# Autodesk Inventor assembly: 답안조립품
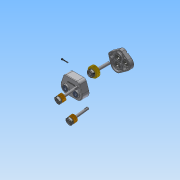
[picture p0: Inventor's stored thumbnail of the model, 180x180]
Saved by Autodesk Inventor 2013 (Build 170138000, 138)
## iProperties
Created: 2014-12
Part Number: 답안조립품
Document SubType Name: Assembly
Designer: Administrator
Author: Administrator
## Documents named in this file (14)
- C:\Users\Administrator\Desktop\441209V1016\441209V1016\답안조립품.iam
- C:\Users\Administrator\Desktop\441209V1016\441209V1016\본체.ipt
- C:\Users\Administrator\Desktop\441209V1016\441209V1016\M 5 x 35.ipt
- C:\Users\Administrator\Desktop\441209V1016\441209V1016\멈춤링.ipt
- C:\Users\Administrator\Desktop\441209V1016\441209V1016\메인기어.ipt
- C:\Users\Administrator\Desktop\441209V1016\441209V1016\메인축.ipt
- C:\Users\Administrator\Desktop\441209V1016\441209V1016\베어링- 6202.ipt
- C:\Users\Administrator\Desktop\441209V1016\441209V1016\베어링- 6203.ipt
- C:\Users\Administrator\Desktop\441209V1016\441209V1016\서브기어.ipt
- C:\Users\Administrator\Desktop\441209V1016\441209V1016\서브축.ipt
- C:\Users\Administrator\Desktop\441209V1016\441209V1016\오일시일-D-15.ipt
- C:\Users\Administrator\Desktop\441209V1016\441209V1016\오일시일-D-17.ipt
- C:\Users\Administrator\Desktop\441209V1016\441209V1016\커버.ipt
- C:\Users\Administrator\Desktop\441209V1016\441209V1016\키5x5.ipt
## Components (13 placed, 6 different names)
1. KS B 1003 - 미터 M 5 x 35:1
2. KS B 1336 17 x 1:1
3. KS B 2023 6202 - 15 x 35 x 11:1
4. KS B 2023 6203 - 17 x 40 x 12:1
5. KS B 2804 D D - 15 30 7:1 — 플러쉬:3
6. KS B 2804 D D - 17 30 8:1 — 플러쉬:1
7. KS B 1336 17 x 1:2
8. KS B 1336 17 x 1:3
9. KS B 2023 6202 - 15 x 35 x 11:2
10. KS B 2023 6203 - 17 x 40 x 12:2
11. KS B 2023 6203 - 17 x 40 x 12:3
12. KS B 2023 6203 - 17 x 40 x 12:4
13. KS B 2804 D D - 15 30 7:2 — 플러쉬:2
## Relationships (3: Flush 3)
- 플러쉬:1 [Flush]: KS B 2804 D D - 17 30 8:1
- 플러쉬:2 [Flush]: KS B 2804 D D - 15 30 7:2
- 플러쉬:3 [Flush]: KS B 2804 D D - 15 30 7:1
